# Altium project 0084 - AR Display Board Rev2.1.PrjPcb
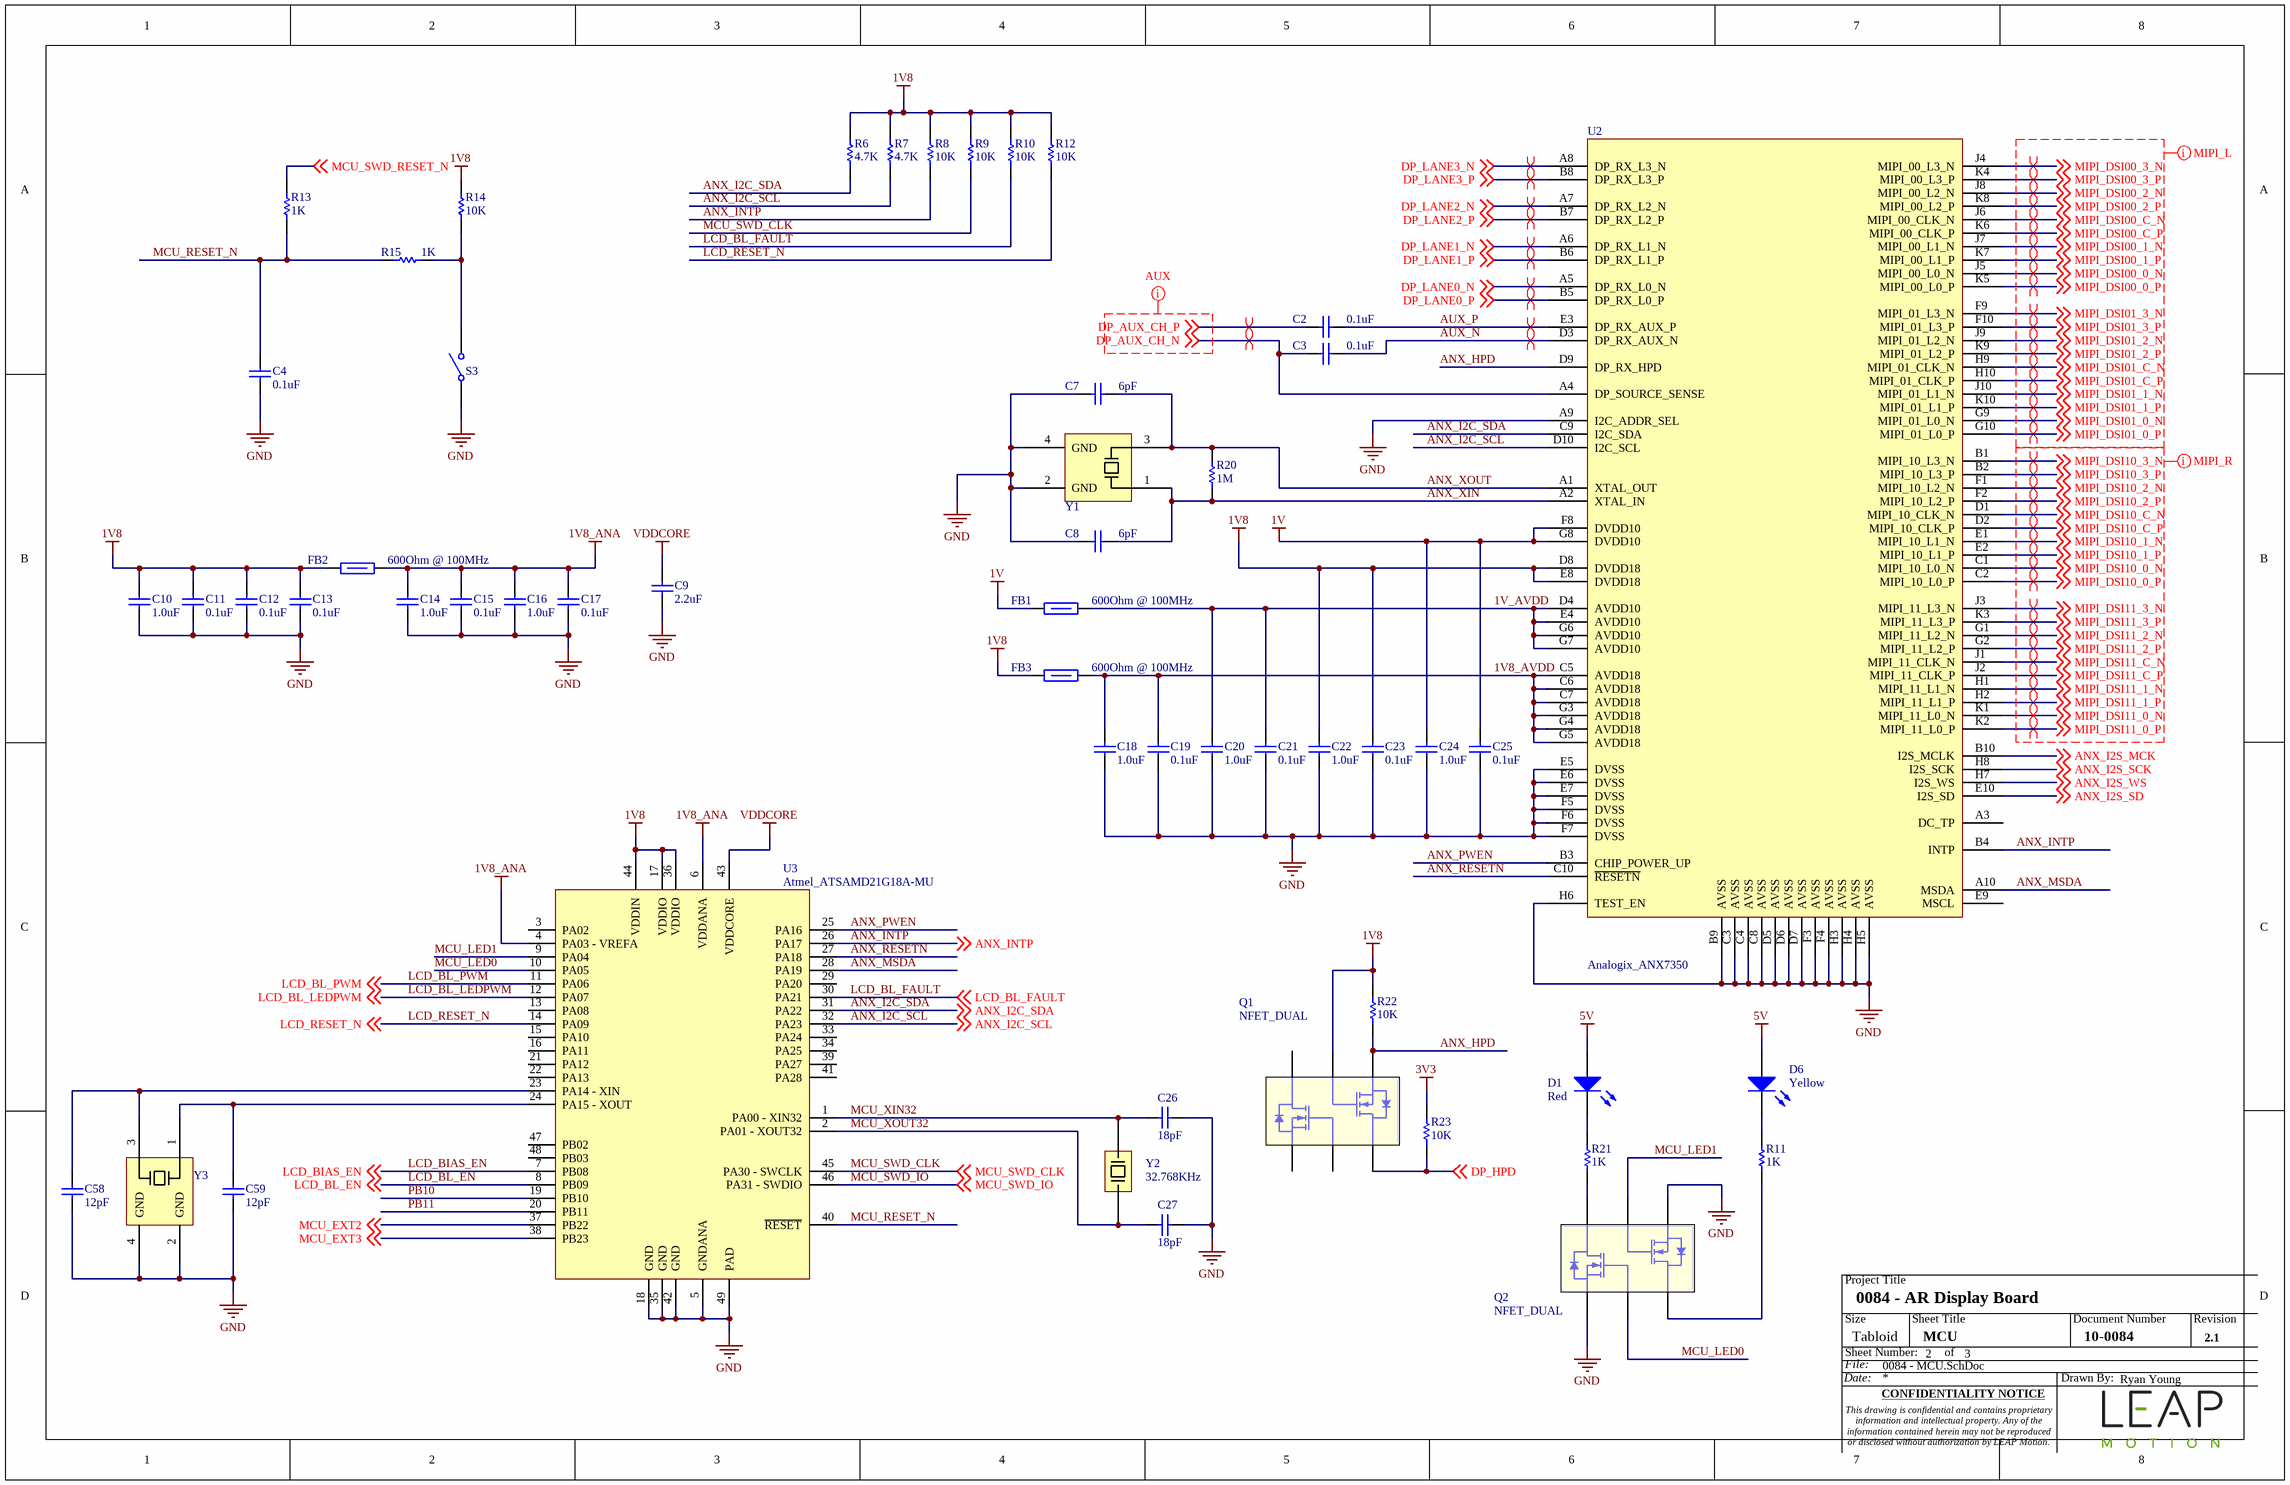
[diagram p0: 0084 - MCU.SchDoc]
BoardColor: Matte Black; BoardThickness: 1.6mm; CageCode: XXXXX; DrawnBy: Ryan Young; DrawnByDate: 3/18/2018; DwgNo: 12-0084; DwgTitle: 0084 - AR Display Board; Engineer: Ryan Young; EngineerDate: 3/18/2018; FabricatedNo: 45-0084 Rev. 002; GerberNo: 11-0084; InnerCopperWeight: 0.5 oz; IPCclass: Class 2; Issued: Ahmad Abbas; IssuedDate: 3/18/2018; OuterCopperWeight: 0.5 oz; PCBAssemblyNo: 65-0084 Rev. 002; ProjectTitle: 0084 - AR Display Board; Revision: 002; SchNo: 10-0084
3 sheets, 141 parts. Net scope: global (net labels, ports and power ports of the same name join across sheets).
Board file: 0084 - AR Display Board Rev2.1.PcbDoc
Sheets:
  0084 - MCU.SchDoc
  0084 - Power.SchDoc
  0084 - Connectors.SchDoc

## Sheet 0084 - MCU.SchDoc: 0084 - AR Display Board
size Tabloid; Date: 3/18/2018; DrawnBy: Ryan Young; DocumentNumber: 1; Revision: 2.1; SheetNumber: 2; SheetTotal: 3; SheetTitle: MCU; PageSetup: Record=PageOptions¦CenterHorizontal=True¦CenterVertical=True¦PrintScale=0.95¦XCorrection=1.00¦YCorrection=1.00¦PrintKind=0¦BorderSize=5000000¦LeftOffset=0¦BottomOffset=0¦Orientation=2¦PaperLength=1000¦PaperWidth=1000¦Scale=100¦PaperSource=15¦PrintQuality=600¦MediaType=1¦DitherType=10¦PaperKind=Letter (8.5 x 11")¦PrintScaleMode=1

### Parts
C2  0.1uF  [CAPC0201(0603)33_N]
C3  0.1uF  [CAPC0201(0603)33_N]
C4  0.1uF  [CAPC0201(0603)33_N]
C7  6pF  [CAPC0201(0603)33_N]
C8  6pF  [CAPC0201(0603)33_N]
C9  2.2uF  [CAPC0402(1005)60_N]
C10  1.0uF  [CAPC0402(1005)60_N]
C11  0.1uF  [CAPC0201(0603)33_N]
C12  0.1uF  [CAPC0201(0603)33_N]
C13  0.1uF  [CAPC0201(0603)33_N]
C14  1.0uF  [CAPC0402(1005)60_N]
C15  0.1uF  [CAPC0201(0603)33_N]
C16  1.0uF  [CAPC0402(1005)60_N]
C17  0.1uF  [CAPC0201(0603)33_N]
C18  1.0uF  [CAPC0402(1005)60_L]  (no BOM)
C19  0.1uF  [CAPC0201(0603)33_L]  (no BOM)
C20  1.0uF  [CAPC0402(1005)60_L]  (no BOM)
C21  0.1uF  [CAPC0201(0603)33_L]  (no BOM)
C22  1.0uF  [CAPC0402(1005)60_L]  (no BOM)
C23  0.1uF  [CAPC0201(0603)33_L]  (no BOM)
C24  1.0uF  [CAPC0402(1005)60_L]  (no BOM)
C25  0.1uF  [CAPC0201(0603)33_L]  (no BOM)
C26  18pF  [CAPC0201(0603)33_N]
C27  18pF  [CAPC0201(0603)33_N]
C58  12pF  [CAPC0201(0603)33_N]
C59  12pF  [CAPC0201(0603)33_N]
D1  Color: Red  [Dialight_598-8010-107F]
D6  Color: Yellow  [Dialight_598-8040-107F]
FB1  Impedance @ Freq: 600Ohm @ 100MHz  [INDC1608X09N]  (hidden comment: Ferrite Bead)
FB2  Impedance @ Freq: 600Ohm @ 100MHz  [INDC1608X09N]  (hidden comment: Ferrite Bead)
FB3  Impedance @ Freq: 600Ohm @ 100MHz  [INDC1608X09N]  (hidden comment: Ferrite Bead)
Q1  NFET_DUAL  [SOT-563]
Q2  NFET_DUAL  [SOT-563]
R6  4.7K  [RESC0201(0603)_N]
R7  4.7K  [RESC0201(0603)_N]
R8  10K  [RESC0201(0603)_N]
R9  10K  [RESC0201(0603)_N]
R10  10K  [RESC0201(0603)_N]
R11  1K  [RESC0201(0603)_N]
R12  10K  [RESC0201(0603)_N]
R13  1K  [RESC0201(0603)_N]
R14  10K  [RESC0201(0603)_N]
R15  1K  [RESC0201(0603)_N]
R20  1M  [RESC0201(0603)_N]
R21  1K  [RESC0201(0603)_N]
R22  10K  [RESC0201(0603)_N]
R23  10K  [RESC0201(0603)_N]
S3  SW-SPST  [ALPS_SKRPABE010]  (value not drawn)
U2  Analogix_ANX7350  [Analogix_ANX7350]
U3  Atmel_ATSAMD21G18A-MU  [Atmel_ATSAMD21G18A-MU]
Y1  Crystal  [Abracon_ABM11]  (value not drawn)
Y2  Frequency: 32.768KHz  [Abracon_ABS07]  (hidden comment: Crystal_2pin)
Y3  Crystal  [Abracon_ABM11]  (value not drawn)

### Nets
1V: C24.2 C25.2 FB1.1 U2.F8(DVDD10) U2.G8(DVDD10)
1V8: C10.2 C11.2 C12.2 C13.2 C22.2 C23.2 FB2.1 FB3.1 Q1.5(G2) R6.2 R7.2 R8.2 R9.2 R10.2 R12.2 R14.2 R22.2 U2.D8(DVDD18) U2.E8(DVDD18) U3.17(VDDIO) U3.36(VDDIO) U3.44(VDDIN)
1V8_ANA: C14.2 C15.2 C16.2 C17.2 FB2.2 U3.4(PA03_-_VREFA) U3.6(VDDANA)
3V3: R23.1
5V: D1.A D6.A
GND: C4.1 C7.2 C8.2 C9.2 C10.1 C11.1 C12.1 C13.1 C14.1 C15.1 C16.1 C17.1 C18.1 C19.1 C20.1 C21.1 C22.1 C23.1 C24.1 C25.1 C26.2 C27.2 C58.2 C59.2 Q2.1(S1) Q2.4(S2) S3.1(COMMON) U2.A9(I2C_ADDR_SEL) U2.B9(AVSS) U2.C3(AVSS) U2.C4(AVSS) U2.C8(AVSS) U2.D5(AVSS) U2.D6(AVSS) U2.D7(AVSS) U2.E5(DVSS) U2.E6(DVSS) U2.E7(DVSS) U2.F3(AVSS) U2.F4(AVSS) U2.F5(DVSS) U2.F6(DVSS) U2.F7(DVSS) U2.H3(AVSS) U2.H4(AVSS) U2.H5(AVSS) U2.H6(TEST_EN) U3.5(GNDANA) U3.18(GND) U3.35(GND) U3.42(GND) U3.49(PAD) Y1.2(GND) Y1.4(GND) Y3.2(GND) Y3.4(GND)
VDDCORE: C9.1 U3.43(VDDCORE)
1V8_AVDD: C18.2 C19.2 FB3.2 U2.C5(AVDD18) U2.C6(AVDD18) U2.C7(AVDD18) U2.G3(AVDD18) U2.G4(AVDD18) U2.G5(AVDD18)
1V_AVDD: C20.2 C21.2 FB1.2 U2.D4(AVDD10) U2.E4(AVDD10) U2.G6(AVDD10) U2.G7(AVDD10)
ANX_HPD: Q1.4(S2) R22.1 U2.D9(DP_RX_HPD)
ANX_I2C_SCL: R7.1 U2.D10(I2C_SCL) U3.32(PA23) ; off-sheet ANX_I2C_SCL
ANX_I2C_SDA: R6.1 U2.C9(I2C_SDA) U3.31(PA22) ; off-sheet ANX_I2C_SDA
ANX_I2S_MCK: U2.B10(I2S_MCLK) ; off-sheet ANX_I2S_MCK
ANX_I2S_SCK: U2.H8(I2S_SCK) ; off-sheet ANX_I2S_SCK
ANX_I2S_SD: U2.E10(I2S_SD) ; off-sheet ANX_I2S_SD
ANX_I2S_WS: U2.H7(I2S_WS) ; off-sheet ANX_I2S_WS
ANX_INTP: R8.1 U2.B4(INTP) U3.26(PA17) ; off-sheet ANX_INTP
ANX_MSDA: U2.A10(MSDA) U3.28(PA19)
ANX_PWEN: U2.B3(CHIP_POWER_UP) U3.25(PA16)
ANX_RESETN: U2.C10(~{RESETN}) U3.27(PA18)
ANX_XIN: C8.1 R20.1 U2.A2(XTAL_IN) Y1.1(XTAL1)
ANX_XOUT: C7.1 R20.2 U2.A1(XTAL_OUT) Y1.3(XTAL2)
AUX_N: C3.1 U2.D3(DP_RX_AUX_N)
AUX_P: C2.1 U2.E3(DP_RX_AUX_P)
DP_AUX_CH_N: C3.2 U2.A4(DP_SOURCE_SENSE) ; off-sheet DP_AUX_CH_N
DP_AUX_CH_P: C2.2 ; off-sheet DP_AUX_CH_P
DP_HPD: Q1.3(D2) R23.2 ; off-sheet DP_HPD
DP_LANE0_N: U2.A5(DP_RX_L0_N) ; off-sheet DP_LANE0_N
DP_LANE0_P: U2.B5(DP_RX_L0_P) ; off-sheet DP_LANE0_P
DP_LANE1_N: U2.A6(DP_RX_L1_N) ; off-sheet DP_LANE1_N
DP_LANE1_P: U2.B6(DP_RX_L1_P) ; off-sheet DP_LANE1_P
DP_LANE2_N: U2.A7(DP_RX_L2_N) ; off-sheet DP_LANE2_N
DP_LANE2_P: U2.B7(DP_RX_L2_P) ; off-sheet DP_LANE2_P
DP_LANE3_N: U2.A8(DP_RX_L3_N) ; off-sheet DP_LANE3_N
DP_LANE3_P: U2.B8(DP_RX_L3_P) ; off-sheet DP_LANE3_P
LCD_BIAS_EN: U3.7(PB08) ; off-sheet LCD_BIAS_EN
LCD_BL_EN: U3.8(PB09) ; off-sheet LCD_BL_EN
LCD_BL_FAULT: R10.1 U3.30(PA21) ; off-sheet LCD_BL_FAULT
LCD_BL_LEDPWM: U3.12(PA07) ; off-sheet LCD_BL_LEDPWM
LCD_BL_PWM: U3.11(PA06) ; off-sheet LCD_BL_PWM
LCD_RESET_N: R12.1 U3.14(PA09) ; off-sheet LCD_RESET_N
MCU_EXT2: U3.37(PB22) ; off-sheet MCU_EXT2
MCU_EXT3: U3.38(PB23) ; off-sheet MCU_EXT3
MCU_LED0: Q2.2(G1) U3.10(PA05)
MCU_LED1: Q2.5(G2) U3.9(PA04)
MCU_RESET_N: C4.2 R13.2 R15.2 U3.40(~{RESET})
MCU_SWD_CLK: R9.1 U3.45(PA30_-_SWCLK) ; off-sheet MCU_SWD_CLK
MCU_SWD_IO: U3.46(PA31_-_SWDIO) ; off-sheet MCU_SWD_IO
MCU_SWD_RESET_N: R13.1 ; off-sheet MCU_SWD_RESET_N
MCU_XIN32: C26.1 U3.1(PA00_-_XIN32) Y2.1(XTAL2)
MCU_XOUT32: C27.1 U3.2(PA01_-_XOUT32) Y2.0(XTAL1)
MIPI_DSI00_0_N: U2.J5(MIPI_00_L0_N) ; off-sheet MIPI_DSI00_0_N
MIPI_DSI00_0_P: U2.K5(MIPI_00_L0_P) ; off-sheet MIPI_DSI00_0_P
MIPI_DSI00_1_N: U2.J7(MIPI_00_L1_N) ; off-sheet MIPI_DSI00_1_N
MIPI_DSI00_1_P: U2.K7(MIPI_00_L1_P) ; off-sheet MIPI_DSI00_1_P
MIPI_DSI00_2_N: U2.J8(MIPI_00_L2_N) ; off-sheet MIPI_DSI00_2_N
MIPI_DSI00_2_P: U2.K8(MIPI_00_L2_P) ; off-sheet MIPI_DSI00_2_P
MIPI_DSI00_3_N: U2.J4(MIPI_00_L3_N) ; off-sheet MIPI_DSI00_3_N
MIPI_DSI00_3_P: U2.K4(MIPI_00_L3_P) ; off-sheet MIPI_DSI00_3_P
MIPI_DSI00_C_N: U2.J6(MIPI_00_CLK_N) ; off-sheet MIPI_DSI00_C_N
MIPI_DSI00_C_P: U2.K6(MIPI_00_CLK_P) ; off-sheet MIPI_DSI00_C_P
MIPI_DSI01_0_N: U2.G9(MIPI_01_L0_N) ; off-sheet MIPI_DSI01_0_N
MIPI_DSI01_0_P: U2.G10(MIPI_01_L0_P) ; off-sheet MIPI_DSI01_0_P
MIPI_DSI01_1_N: U2.J10(MIPI_01_L1_N) ; off-sheet MIPI_DSI01_1_N
MIPI_DSI01_1_P: U2.K10(MIPI_01_L1_P) ; off-sheet MIPI_DSI01_1_P
MIPI_DSI01_2_N: U2.J9(MIPI_01_L2_N) ; off-sheet MIPI_DSI01_2_N
MIPI_DSI01_2_P: U2.K9(MIPI_01_L2_P) ; off-sheet MIPI_DSI01_2_P
MIPI_DSI01_3_N: U2.F9(MIPI_01_L3_N) ; off-sheet MIPI_DSI01_3_N
MIPI_DSI01_3_P: U2.F10(MIPI_01_L3_P) ; off-sheet MIPI_DSI01_3_P
MIPI_DSI01_C_N: U2.H9(MIPI_01_CLK_N) ; off-sheet MIPI_DSI01_C_N
MIPI_DSI01_C_P: U2.H10(MIPI_01_CLK_P) ; off-sheet MIPI_DSI01_C_P
MIPI_DSI10_0_N: U2.C1(MIPI_10_L0_N) ; off-sheet MIPI_DSI10_0_N
MIPI_DSI10_0_P: U2.C2(MIPI_10_L0_P) ; off-sheet MIPI_DSI10_0_P
MIPI_DSI10_1_N: U2.E1(MIPI_10_L1_N) ; off-sheet MIPI_DSI10_1_N
MIPI_DSI10_1_P: U2.E2(MIPI_10_L1_P) ; off-sheet MIPI_DSI10_1_P
MIPI_DSI10_2_N: U2.F1(MIPI_10_L2_N) ; off-sheet MIPI_DSI10_2_N
MIPI_DSI10_2_P: U2.F2(MIPI_10_L2_P) ; off-sheet MIPI_DSI10_2_P
MIPI_DSI10_3_N: U2.B1(MIPI_10_L3_N) ; off-sheet MIPI_DSI10_3_N
MIPI_DSI10_3_P: U2.B2(MIPI_10_L3_P) ; off-sheet MIPI_DSI10_3_P
MIPI_DSI10_C_N: U2.D1(MIPI_10_CLK_N) ; off-sheet MIPI_DSI10_C_N
MIPI_DSI10_C_P: U2.D2(MIPI_10_CLK_P) ; off-sheet MIPI_DSI10_C_P
MIPI_DSI11_0_N: U2.K1(MIPI_11_L0_N) ; off-sheet MIPI_DSI11_0_N
MIPI_DSI11_0_P: U2.K2(MIPI_11_L0_P) ; off-sheet MIPI_DSI11_0_P
MIPI_DSI11_1_N: U2.H1(MIPI_11_L1_N) ; off-sheet MIPI_DSI11_1_N
MIPI_DSI11_1_P: U2.H2(MIPI_11_L1_P) ; off-sheet MIPI_DSI11_1_P
MIPI_DSI11_2_N: U2.G1(MIPI_11_L2_N) ; off-sheet MIPI_DSI11_2_N
MIPI_DSI11_2_P: U2.G2(MIPI_11_L2_P) ; off-sheet MIPI_DSI11_2_P
MIPI_DSI11_3_N: U2.J3(MIPI_11_L3_N) ; off-sheet MIPI_DSI11_3_N
MIPI_DSI11_3_P: U2.K3(MIPI_11_L3_P) ; off-sheet MIPI_DSI11_3_P
MIPI_DSI11_C_N: U2.J1(MIPI_11_CLK_N) ; off-sheet MIPI_DSI11_C_N
MIPI_DSI11_C_P: U2.J2(MIPI_11_CLK_P) ; off-sheet MIPI_DSI11_C_P
PB10: U3.19(PB10)
PB11: U3.20(PB11)
NetC58_1: C58.1 U3.23(PA14_-_XIN) Y3.3(XTAL2)
NetC59_1: C59.1 U3.24(PA15_-_XOUT) Y3.1(XTAL1)
NetD1_K: D1.K R21.1
NetD6_K: D6.K R11.1
NetQ2_3: Q2.3(D2) R11.2
NetQ2_6: Q2.6(D1) R21.2
NetR14_1: R14.1 R15.1 S3.2(NO)

Not connected (* = marked no-connect by the designer): Q1 1(S1) 2(G1) 6(D1); U2 A3(DC_TP) E9(MSCL); U3 3(PA02) 13(PA08) 15(PA10) 16(PA11) 21(PA12) 22(PA13) 29(PA20) 33(PA24) 34(PA25) 39(PA27) 41(PA28) 47(PB02) 48(PB03)

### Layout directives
differential pair: AUX_N, AUX_P, DP_AUX_CH_N, DP_AUX_CH_P, DP_LANE0_N, DP_LANE0_P, DP_LANE1_N, DP_LANE1_P, DP_LANE2_N, DP_LANE2_P, DP_LANE3_N, DP_LANE3_P, MIPI_DSI00_0_N, MIPI_DSI00_0_P, MIPI_DSI00_1_N, MIPI_DSI00_1_P, MIPI_DSI00_2_N, MIPI_DSI00_2_P, MIPI_DSI00_3_N, MIPI_DSI00_3_P, MIPI_DSI00_C_N, MIPI_DSI00_C_P, MIPI_DSI01_0_N, MIPI_DSI01_0_P, MIPI_DSI01_1_N, MIPI_DSI01_1_P, MIPI_DSI01_2_N, MIPI_DSI01_2_P, MIPI_DSI01_3_N, MIPI_DSI01_3_P, MIPI_DSI01_C_N, MIPI_DSI01_C_P, MIPI_DSI10_0_N, MIPI_DSI10_0_P, MIPI_DSI10_1_N, MIPI_DSI10_1_P, MIPI_DSI10_2_N, MIPI_DSI10_2_P, MIPI_DSI10_3_N, MIPI_DSI10_3_P, MIPI_DSI10_C_N, MIPI_DSI10_C_P, MIPI_DSI11_0_N, MIPI_DSI11_0_P, MIPI_DSI11_1_N, MIPI_DSI11_1_P, MIPI_DSI11_2_N, MIPI_DSI11_2_P, MIPI_DSI11_3_N, MIPI_DSI11_3_P, MIPI_DSI11_C_N, MIPI_DSI11_C_P
net class MIPI_L: MIPI_DSI00_0_N, MIPI_DSI00_0_P, MIPI_DSI00_1_N, MIPI_DSI00_1_P, MIPI_DSI00_2_N, MIPI_DSI00_2_P, MIPI_DSI00_3_N, MIPI_DSI00_3_P, MIPI_DSI00_C_N, MIPI_DSI00_C_P, MIPI_DSI01_0_N, MIPI_DSI01_0_P, MIPI_DSI01_1_N, MIPI_DSI01_1_P, MIPI_DSI01_2_N, MIPI_DSI01_2_P, MIPI_DSI01_3_N, MIPI_DSI01_3_P, MIPI_DSI01_C_N, MIPI_DSI01_C_P
net class MIPI_R: MIPI_DSI10_0_N, MIPI_DSI10_0_P, MIPI_DSI10_1_N, MIPI_DSI10_1_P, MIPI_DSI10_2_N, MIPI_DSI10_2_P, MIPI_DSI10_3_N, MIPI_DSI10_3_P, MIPI_DSI10_C_N, MIPI_DSI10_C_P, MIPI_DSI11_0_N, MIPI_DSI11_0_P, MIPI_DSI11_1_N, MIPI_DSI11_1_P, MIPI_DSI11_2_N, MIPI_DSI11_2_P, MIPI_DSI11_3_N, MIPI_DSI11_3_P, MIPI_DSI11_C_N, MIPI_DSI11_C_P
net class AUX: DP_AUX_CH_N, DP_AUX_CH_P

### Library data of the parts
C2-C4 C11-C13 C15 C17 C19 C21 C23 C25 = CAP_0060: Capacitor, 0.1uF, 10V, 10%, 0201, Ceramic, X5R; Manufacturer: Murata; Manufacturer P/N: GRM033R61A104KE15D; Polarity: No; Temp Range: -55C - 85C
C7 C8 = CAP_0064: Capacitor, 6pF, 50V, 0.1pF, 0201, Ceramic, C0G(NP0); Manufacturer: Murata; Manufacturer P/N: GRM0335C1H6R0BA01D; Polarity: No; Temp Range: -55C - 125C
C9 = CAP_0016: Capacitor, 2.2uF, 6.3V, 20%, 0402, Ceramic, X5R; Manufacturer: TDK; Manufacturer P/N: C1005X5R0J225M050BC; Polarity: No; Temp Range: -55C - 85C
C10 C14 C16 C18 C20 C22 C24 = CAP_0023: Capacitor, 1.0uF, 10V, 10%, 0402, Ceramic, X5R; Manufacturer: TDK; Manufacturer P/N: C1005X5R1A105K050BB; Polarity: No; Temp Range: -55C - 85C
C26 C27 = CAP_0066: Capacitor, 18pF, 50V, 2%, 0201, Ceramic, C0G(NP0); Manufacturer: Murata; Manufacturer P/N: GRM0335C1H180GA01D; Polarity: No; Temp Range: -55C - 125C
C58 C59 = CAP_0065: Capacitor, 12pF, 50V, 2%, 0201, Ceramic, C0G(NP0); Manufacturer: Murata; Manufacturer P/N: GRM0335C1H120GA01D; Polarity: No; Temp Range: -55C - 125C
D1 = LED_0017: LED, 635nm, 140deg, , 20mA, , 1.6mm x 0.8mm, -30C - 85C; Manufacturer: Dialight; Manufacturer P/N: 598-8010-107F; Vf: 1.7V; Radiant Intensity (mW/sr): 40mcd
D6 = LED_0034: LED, 593nm, 140deg, , 20mA, , 1.6mm x 0.8mm, -30C - 85C; Manufacturer: Dialight; Manufacturer P/N: 598-8040-107F; Vf: 2V; Radiant Intensity (mW/sr): 130mcd
FB1-FB3 = FB_0001: FERRITE CHIP BEAD 600 OHM SMD; Manufacturer: TDK; Manufacturer P/N: MPZ1608S601A; Current Rating: 1A; DCR: 150mOhm
Q1 Q2 = NFET_0009: Transistor, NFET_DUAL, 2.2Ohm, 200mA, 120mW, 	SOT-563, -55C - 150C; Manufacturer: Rohm Semiconductor; Manufacturer P/N: EM6K34T2CR; Display: NFET_DUAL, 	SOT-563
R6 R7 = RES_0040: Resistor, 4.7K, 1/20W, 1%, 0201; Manufacturer: Panasonic Electronic Components; Manufacturer P/N: ERJ-1GEF4701C; Display Value: 4.7K, 0201; Temp Range: -55C - 125C
R8-R10 R12 R14 R22 R23 = RES_0014: Resistor, 10K, 1/20W, 5%, 0201; Manufacturer: Panasonic Electronic Components; Manufacturer P/N: ERJ-1GEJ103C; Display Value: 10K, 0201; Temp Range: -55C - 155C
R11 R13 R15 R21 = RES_0036: Resistor, 1K, 1/20W, 5%, 0201; Manufacturer: Panasonic Electronic Components; Manufacturer P/N: ERJ-1GEJ102C; Display Value: 1K, 0201; Temp Range: -55C - 125C
R20 = RES_0178: Resistor, 1M, 1/20W, 1%, 0201; Manufacturer: Panasonic Electronic Components; Manufacturer P/N: ERJ-1GEF1004C; Display Value: 1M, 0201; Temp Range: -55C - 125C
S3 = SWT_0006: Switch, SPST-NO, Button, 4.6mm x 3.2mm; Manufacturer: ALPS; Manufacturer P/N: SKRPABE010; Display: Switch, SW-SPST
U2 = IC_0196: DisplayPort 1.4-to-Dual MIPI Output Converter
U3 = IC_0197: IC MCU 32BIT 256KB FLASH 48QFN; Manufacturer: Atmel
Y1 = XTAL_0025: Crystal, 24MHz, 6pF, 4-SMD (2x1.6); Manufacturer: Abracon; Manufacturer P/N: XRCGB24M000F2P0R0; Tolerance: 20ppm
Y2 = XTAL_0023: Crystal, 32.768KHz, 12.5pF, 2-SMD(3.2x1.5); Manufacturer: Abracon; Manufacturer P/N: ABS07-32.768KHZ-T; Tolerance: 20 ppm
Y3 = XTAL_0024: Crystal, 16MHz, 10pF, 4-SMD (2x1.6); Manufacturer: Abracon; Manufacturer P/N: ABM11-16.000MHZ-D2X-T3; Tolerance: 20ppm

## Sheet 0084 - Power.SchDoc: 0084 - AR Display
size Tabloid; Date: 3/18/2018; DrawnBy: Ryan Young; DocumentNumber: 1; Revision: 2.1; SheetNumber: 1; SheetTotal: 3; SheetTitle: Power; PageSetup: Record=PageOptions¦CenterHorizontal=True¦CenterVertical=True¦PrintScale=0.95¦XCorrection=1.00¦YCorrection=1.00¦PrintKind=0¦BorderSize=5000000¦LeftOffset=0¦BottomOffset=0¦Orientation=2¦PaperLength=1000¦PaperWidth=1000¦Scale=100¦PaperSource=15¦PrintQuality=600¦MediaType=1¦DitherType=10¦PaperKind=Letter (8.5 x 11")¦PrintScaleMode=1
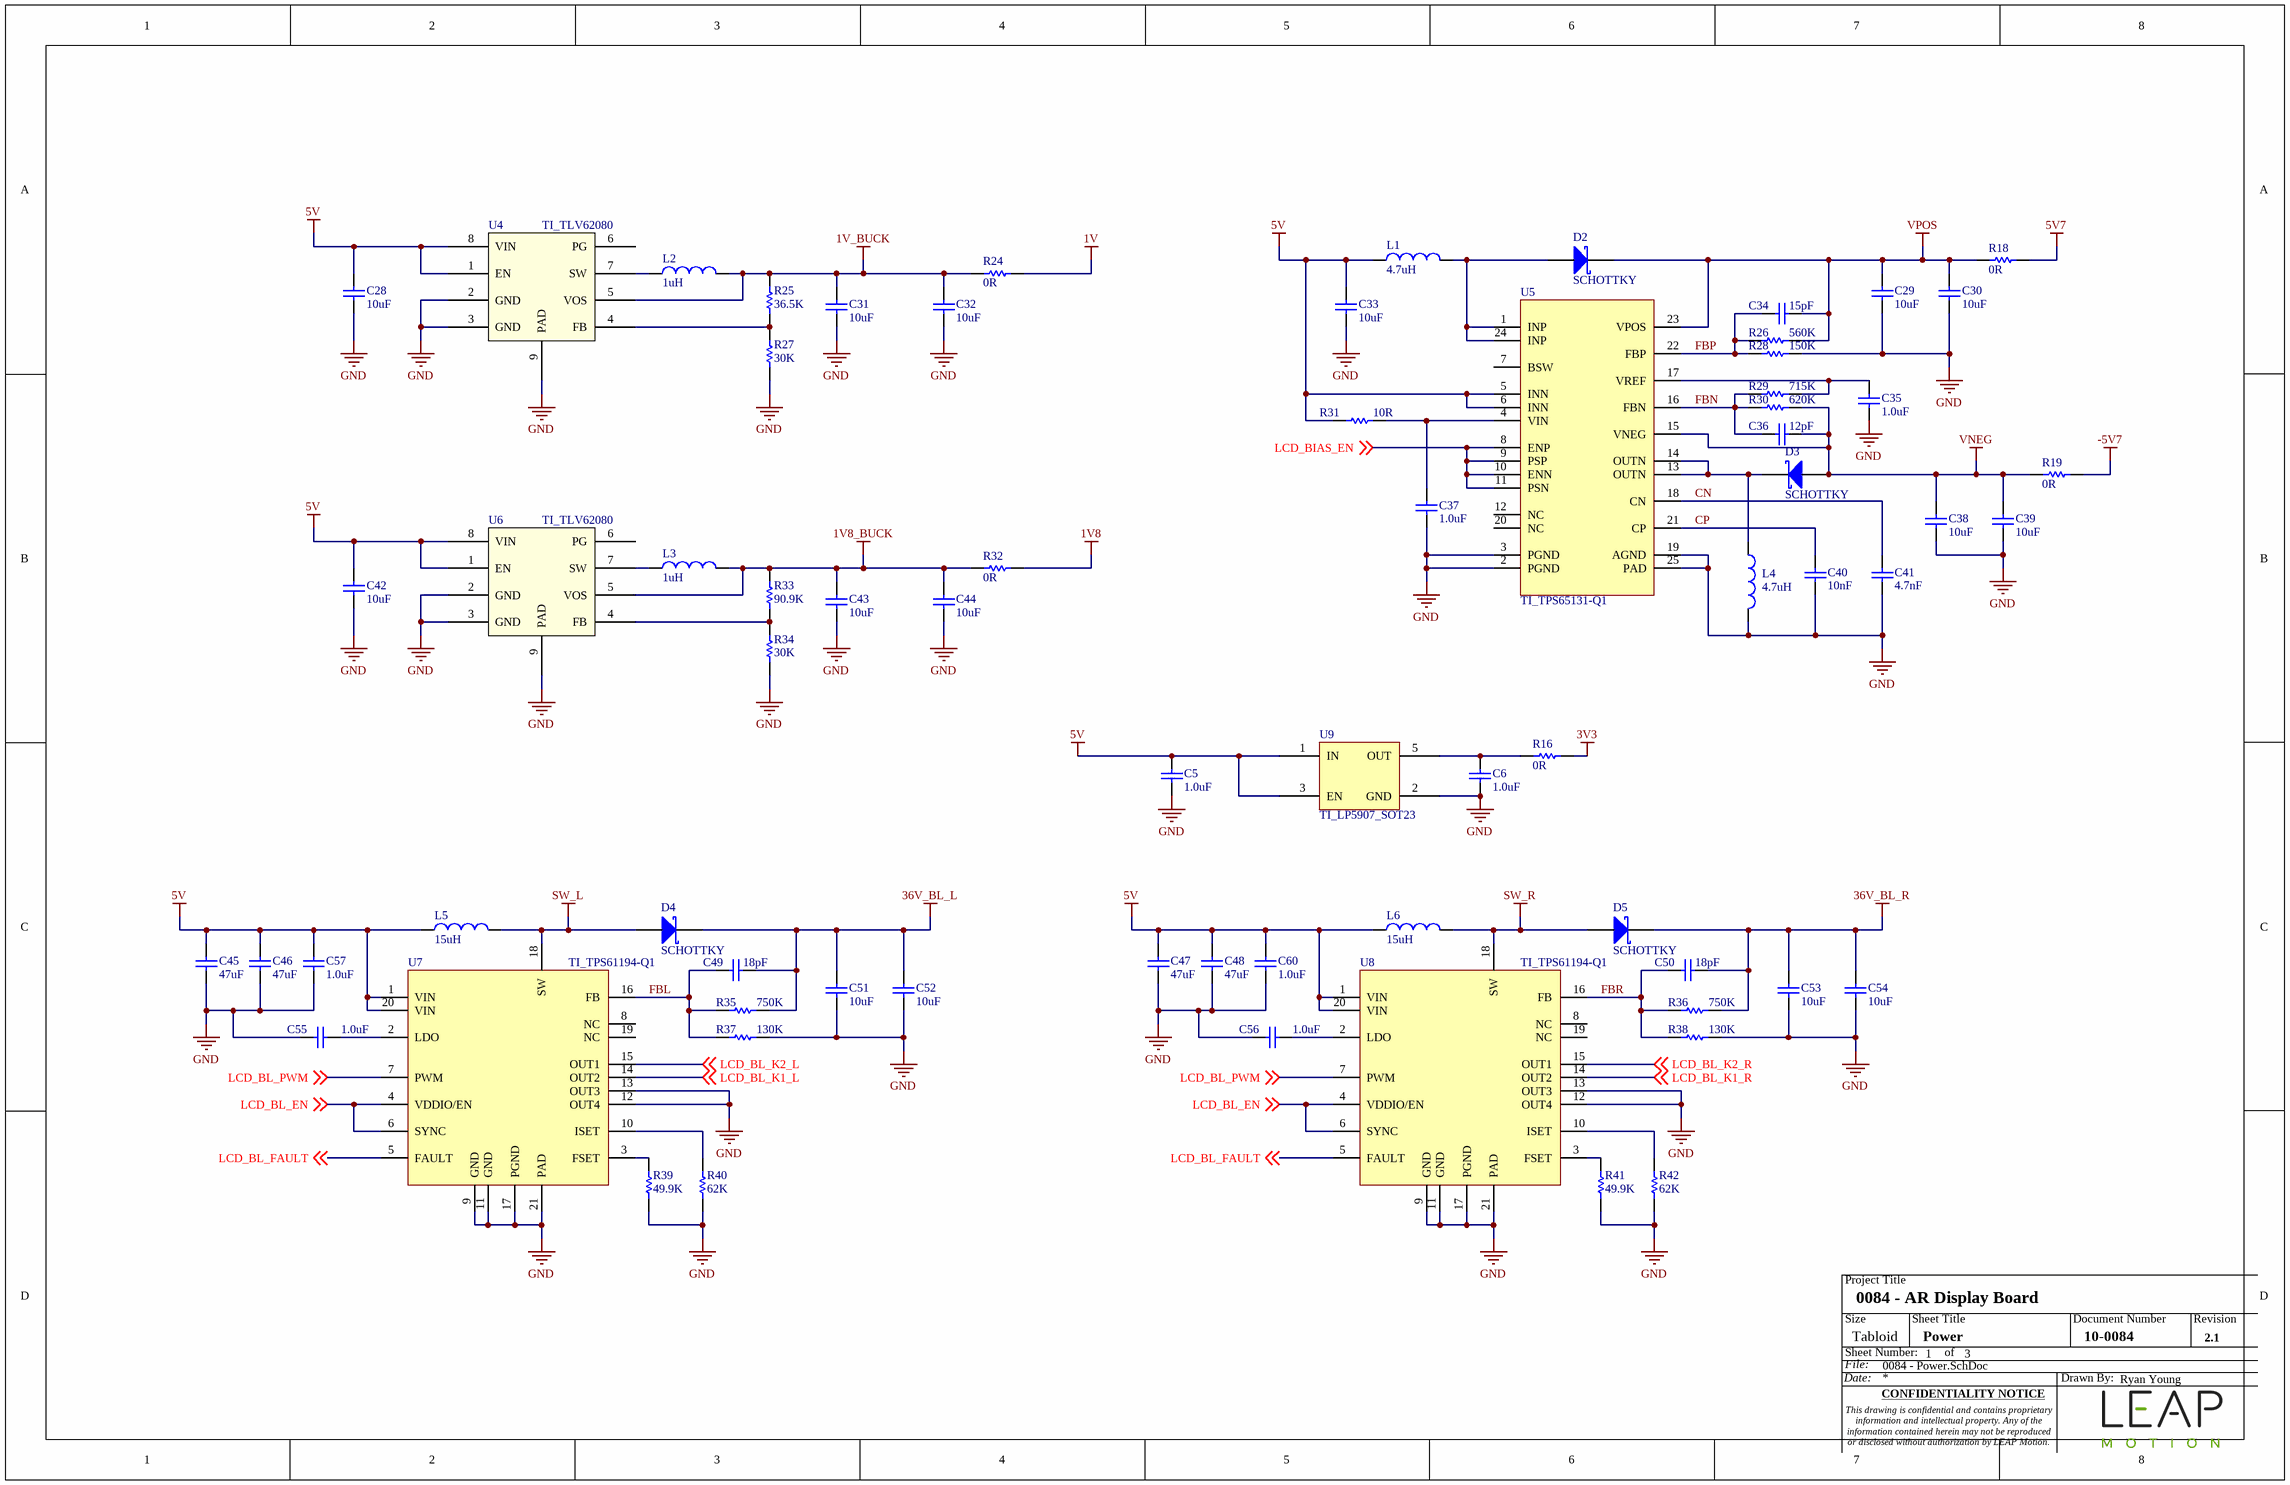
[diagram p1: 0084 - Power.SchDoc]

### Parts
C5  1.0uF  [CAPC0402(1005)60_N]
C6  1.0uF  [CAPC0402(1005)60_N]
C28  10uF  [CAPC0603(1608)100_N]
C29  10uF  [CAPC0603(1608)100_N]
C30  10uF  [CAPC0603(1608)100_N]
C31  10uF  [CAPC0603(1608)100_N]
C32  10uF  [CAPC0603(1608)100_N]
C33  10uF  [CAPC0603(1608)100_N]
C34  15pF  [CAPC0201(0603)33_N]
C35  1.0uF  [CAPC0402(1005)60_N]
C36  12pF  [CAPC0201(0603)33_N]
C37  1.0uF  [CAPC0402(1005)60_N]
C38  10uF  [CAPC0603(1608)100_N]
C39  10uF  [CAPC0603(1608)100_N]
C40  10nF  [CAPC0402(1005)60_N]
C41  4.7nF  [CAPC0402(1005)60_N]
C42  10uF  [CAPC0603(1608)100_N]
C43  10uF  [CAPC0603(1608)100_N]
C44  10uF  [CAPC0603(1608)100_N]
C45  47uF  [CAPC0805(2012)100_N]
C46  47uF  [CAPC0805(2012)100_N]
C47  47uF  [CAPC0805(2012)100_N]
C48  47uF  [CAPC0805(2012)100_N]
C49  18pF  [CAPC0201(0603)33_N]
C50  18pF  [CAPC0201(0603)33_N]
C51  10uF  [CAPC1206(3216)170_N]
C52  10uF  [CAPC1206(3216)170_N]
C53  10uF  [CAPC1206(3216)170_N]
C54  10uF  [CAPC1206(3216)170_N]
C55  1.0uF  [CAPC0402(1005)60_N]
C56  1.0uF  [CAPC0402(1005)60_N]
C57  1.0uF  [CAPC0402(1005)60_N]
C60  1.0uF  [CAPC0402(1005)60_N]
D2  SCHOTTKY  [Toshiba_CUS10S40,H3F]
D3  SCHOTTKY  [Toshiba_CUS10S40,H3F]
D4  SCHOTTKY  [Toshiba_CUS10S40,H3F]
D5  SCHOTTKY  [Toshiba_CUS10S40,H3F]
L1  4.7uH  [INDC2520X10N]
L2  1uH  [INDC2520X10N]
L3  1uH  [INDC2520X10N]
L4  4.7uH  [INDC2520X10N]
L5  15uH  [Coilcraft_XAL4040-153MEB]
L6  15uH  [Coilcraft_XAL4040-153MEB]
R16  0R  [RESC0402(1005)_N]
R18  0R  [RESC0402(1005)_N]
R19  0R  [RESC0402(1005)_N]
R24  0R  [RESC0402(1005)_N]
R25  36.5K  [RESC0201(0603)_N]
R26  560K  [RESC0201(0603)_N]
R27  30K  [RESC0201(0603)_N]
R28  150K  [RESC0201(0603)_N]
R29  715K  [RESC0201(0603)_N]
R30  620K  [RESC0201(0603)_N]
R31  10R  [RESC0402(1005)_N]
R32  0R  [RESC0402(1005)_N]
R33  90.9K  [RESC0201(0603)_N]
R34  30K  [RESC0201(0603)_N]
R35  750K  [RESC0201(0603)_N]
R36  750K  [RESC0201(0603)_N]
R37  130K  [RESC0201(0603)_N]
R38  130K  [RESC0201(0603)_N]
R39  49.9K  [RESC0201(0603)_N]
R40  62K  [RESC0201(0603)_N]
R41  49.9K  [RESC0201(0603)_N]
R42  62K  [RESC0201(0603)_N]
U4  TI_TLV62080  [TI_TLV62080]
U5  TI_TPS65131-Q1  [TI_TPS65131-Q1]
U6  TI_TLV62080  [TI_TLV62080]
U7  TI_TPS61194-Q1  [TI_TPS61194-Q1]
U8  TI_TPS61194-Q1  [TI_TPS61194-Q1]
U9  TI_LP5907_SOT23  [TI_LP5907_SOT23]

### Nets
1V: R24.2
1V8: R32.2
1V8_BUCK: C43.2 C44.2 L3.2 R32.1 R33.2 U6.5(VOS)
1V_BUCK: C31.2 C32.2 L2.2 R24.1 R25.2 U4.5(VOS)
3V3: R16.2
5V: C5.1 C28.2 C33.2 C42.2 C45.2 C46.2 C47.2 C48.2 C57.2 C60.2 L1.1 L5.1 L6.1 R31.1 U4.1(EN) U4.8(VIN) U5.5(INN) U5.6(INN) U6.1(EN) U6.8(VIN) U7.1(VIN) U7.20(VIN) U8.1(VIN) U8.20(VIN) U9.1(IN) U9.3(EN)
5V7: R18.2
36V_BL_L: C49.1 C51.2 C52.2 D4.K R35.1
36V_BL_R: C50.1 C53.2 C54.2 D5.K R36.1
-5V7: R19.2
GND: C5.2 C6.2 C28.1 C29.1 C30.1 C31.1 C32.1 C33.1 C35.2 C37.1 C38.1 C39.1 C40.2 C41.2 C42.1 C43.1 C44.1 C45.1 C46.1 C47.1 C48.1 C51.1 C52.1 C53.1 C54.1 C55.2 C56.2 C57.1 C60.1 L4.2 R27.1 R28.1 R34.1 R37.1 R38.1 R39.1 R40.1 R41.1 R42.1 U4.2(GND) U4.3(GND) U4.9(PAD) U5.2(PGND) U5.3(PGND) U5.19(AGND) U5.25(PAD) U6.2(GND) U6.3(GND) U6.9(PAD) U7.9(GND) U7.11(GND) U7.12(OUT4) U7.13(OUT3) U7.17(PGND) U7.21(PAD) U8.9(GND) U8.11(GND) U8.12(OUT4) U8.13(OUT3) U8.17(PGND) U8.21(PAD) U9.2(GND)
SW_L: D4.A L5.2 U7.18(SW)
SW_R: D5.A L6.2 U8.18(SW)
VNEG: C36.1 C38.2 C39.2 D3.A R19.1 R30.1 U5.15(VNEG)
VPOS: C29.2 C30.2 C34.1 D2.K R18.1 R26.1 U5.23(VPOS)
CN: C41.1 U5.18(CN)
CP: C40.1 U5.21(CP)
FBL: C49.2 R35.2 R37.2 U7.16(FB)
FBN: C36.2 R29.2 R30.2 U5.16(FBN)
FBP: C34.2 R26.2 R28.2 U5.22(FBP)
FBR: C50.2 R36.2 R38.2 U8.16(FB)
LCD_BIAS_EN: U5.8(ENP) U5.9(PSP) U5.10(ENN) U5.11(PSN) ; off-sheet LCD_BIAS_EN
LCD_BL_EN: U7.4(VDDIO/EN) U7.6(SYNC) U8.4(VDDIO/EN) U8.6(SYNC) ; off-sheet LCD_BL_EN
LCD_BL_FAULT: U7.5(FAULT) U8.5(FAULT) ; off-sheet LCD_BL_FAULT
LCD_BL_K1_L: U7.14(OUT2) ; off-sheet LCD_BL_K1_L
LCD_BL_K1_R: U8.14(OUT2) ; off-sheet LCD_BL_K1_R
LCD_BL_K2_L: U7.15(OUT1) ; off-sheet LCD_BL_K2_L
LCD_BL_K2_R: U8.15(OUT1) ; off-sheet LCD_BL_K2_R
LCD_BL_PWM: U7.7(PWM) U8.7(PWM) ; off-sheet LCD_BL_PWM
NetC6_1: C6.1 R16.1 U9.5(OUT)
NetC35_1: C35.1 R29.1 U5.17(VREF)
NetC37_2: C37.2 R31.2 U5.4(VIN)
NetC55_1: C55.1 U7.2(LDO)
NetC56_1: C56.1 U8.2(LDO)
NetD2_A: D2.A L1.2 U5.1(INP) U5.24(INP)
NetD3_K: D3.K L4.1 U5.13(OUTN) U5.14(OUTN)
NetL2_1: L2.1 U4.7(SW)
NetL3_1: L3.1 U6.7(SW)
NetR25_1: R25.1 R27.2 U4.4(FB)
NetR33_1: R33.1 R34.2 U6.4(FB)
NetR39_2: R39.2 U7.3(FSET)
NetR40_2: R40.2 U7.10(ISET)
NetR41_2: R41.2 U8.3(FSET)
NetR42_2: R42.2 U8.10(ISET)

Not connected (* = marked no-connect by the designer): U4 6(PG); U5 7(BSW) 12(NC) 20(NC); U6 6(PG); U7 8(NC) 19(NC); U8 8(NC) 19(NC); U9 4(NC)

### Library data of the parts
C5 C6 C35 C37 C40 C41 C55-C57 C60 = CAP_0023: as C10 on sheet 0084 - MCU
C28-C33 C38 C39 C42-C44 = CAP_0069: Capacitor, 10uF, 10V, 10%, 0603, Ceramic, X5R; Manufacturer: Murata; Manufacturer P/N: GRM188R61A106KE69D; Polarity: No; Temp Range: -55C - 85C
C34 = CAP_0067: Capacitor, 15pF, 50V, 2%, 0201, Ceramic, C0G(NP0); Manufacturer: Murata; Manufacturer P/N: GRM0335C1H150GA01D; Polarity: No; Temp Range: -55C - 125C
C36 = CAP_0065: as C58 on sheet 0084 - MCU
C45-C48 = CAP_0050: Capacitor, 47uF, 10V, 20%, 0805, Ceramic, X5R; Manufacturer: Murata; Manufacturer P/N: GRM21BR61A476ME15L; Polarity: No; Temp Range: -55C-125C
C49 C50 = CAP_0066: as C26 on sheet 0084 - MCU
C51-C54 = CAP_0068: Capacitor, 10uF, 50V, 10%, 1206, Ceramic, X7R; Manufacturer: Samsung; Manufacturer P/N: CL31B106KBHNNNE; Polarity: No; Temp Range: -55C - 125C
D2-D5 = DIODE_0020: Diode, -40C - 150C, SOD-323; Manufacturer: Toshiba; Manufacturer P/N: CUS10S40,H3F
L1 L4 = IND_0023: FIXED IND 4.7UH 1.4A 216 MOHM; Manufacturer: Murata; Manufacturer P/N: DFE252012R-H-4R7M=P2; Tolerance: 20%; Shielding: Shielded
L2 L3 = IND_0001: INDUCTOR 1.0UH 20% 1600MA 1008; Manufacturer: Murata; Manufacturer P/N: LQM2HPN1R0MG0L; Current Rating: 1.6A; Shielding: Shielded; DCR: 68.75mOhm
L5 L6 = IND_0026: Fixed Inductors XAL4040 AEC-Q200 15 uH 20 % 2.8 A; Manufacturer: Coilcraft; Manufacturer P/N: XAL4040-153MEB; Current Rating: 2.8A; Tolerance: 20%; Shielding: Shielded; DCR: 120mOhm
R16 R18 R19 R24 R32 = RES_0006: Resistor, 0R, 1/10W, Jumper, 0402; Manufacturer: Panasonic Electronic Components; Manufacturer P/N: ERJ-2GE0R00X; Display Value: 0R, 0402; Temp Range: -55C - 155C
R25 = RES_0176: Resistor, 36.5K, 1/20W, 1%, 0201; Manufacturer: Panasonic Electronic Components; Manufacturer P/N: ERJ-1GEF3652C; Display Value: 36.5K, 0201; Temp Range: -55C - 125C
R26 = RES_0194: Resistor, 560K, 1/20W, 1%, 0201; Manufacturer: Yageo; Manufacturer P/N: RC0201FR-07560KL; Display Value: 560K, 0201; Temp Range: -55C - 125C
R27 R34 = RES_0175: Resistor, 30K, 1/20W, 1%, 0201; Manufacturer: Panasonic Electronic Components; Manufacturer P/N: ERJ-1GEF3002C; Display Value: 30K, 0201; Temp Range: -55C - 125C
R28 = RES_0173: Resistor, 150K, 1/20W, 1%, 0201; Manufacturer: Panasonic Electronic Components; Manufacturer P/N: ERJ-1GEF1503C; Display Value: 150K, 0201; Temp Range: -55C - 125C
R29 = RES_0195: Resistor, 715K, 1/20W, 1%, 0201; Manufacturer: Yageo; Manufacturer P/N: RC0201FR-07715KL; Display Value: 715K, 0201; Temp Range: -55C - 125C
R30 = RES_0174: Resistor, 620K, 1/20W, 1%, 0201; Manufacturer: Panasonic Electronic Components; Manufacturer P/N: ERJ-1GEF6203C; Display Value: 620K, 0201; Temp Range: -55C - 125C
R31 = RES_0094: Resistor, 10R, 1/10W, 1%, 0402; Manufacturer: Panasonic; Manufacturer P/N: ERJ-2RKF10R0X; Display Value: 10R, 0402; Temp Range: -55C - 155C
R33 = RES_0177: Resistor, 90.9K, 1/20W, 1%, 0201; Manufacturer: Panasonic Electronic Components; Manufacturer P/N: ERJ-1GEF9092C; Display Value: 90.9K, 0201; Temp Range: -55C - 125C
R35 R36 = RES_0169: Resistor, 750K, 1/20W, 1%, 0201; Manufacturer: Panasonic Electronic Components; Manufacturer P/N: ERJ-1GEF7503C; Display Value: 750K, 0201; Temp Range: -55C - 125C
R37 R38 = RES_0170: Resistor, 130K, 1/20W, 1%, 0201; Manufacturer: Panasonic Electronic Components; Manufacturer P/N: ERJ-1GEF1303C; Display Value: 130K, 0201; Temp Range: -55C - 125C
R39 R41 = RES_0067: Resistor, 49.9K, 1/20W, 1%, 0201; Manufacturer: Panasonic Electronic Components; Manufacturer P/N: ERJ-1GEF4992C; Display Value: 49.9K, 0201; Temp Range: -55C - 125C
R40 R42 = RES_0071: Resistor, 62K, 1/20W, 1%, 0201; Manufacturer: Panasonic Electronic Components; Manufacturer P/N: P62.0KABDKR-ND; Display Value: 62K, 0201; Temp Range: -55C - 125C
U4 U6 = IC_0195: IC REG BUCK ADJ 1.2A SYNC 8WSON; Manufacturer: TI
U5 = IC_0199: IC REG BCK BST INV ADJ DL 24VQFN; Manufacturer: TI
U7 U8 = IC_0200: IC LED DRIVER 20TSSOP; Manufacturer: TI
U9 = IC_0118: 3.3 V LDO Voltage Regulators 250mA Ultra-Lo Noise LDO Reg; Manufacturer: TI; Manufacturer P/N: LP5907MFX-3.3NPB

## Sheet 0084 - Connectors.SchDoc: 0084 - AR Display Board
size Tabloid; Date: 3/18/2018; DrawnBy: Ryan Young; DocumentNumber: 1; Revision: 2.1; SheetNumber: 3; SheetTotal: 3; SheetTitle: Connectors; PageSetup: Record=PageOptions¦CenterHorizontal=True¦CenterVertical=True¦PrintScale=0.95¦XCorrection=1.00¦YCorrection=1.00¦PrintKind=0¦BorderSize=5000000¦LeftOffset=0¦BottomOffset=0¦Orientation=2¦PaperLength=1000¦PaperWidth=1000¦Scale=100¦PaperSource=15¦PrintQuality=600¦MediaType=1¦DitherType=10¦PaperKind=Letter (8.5 x 11")¦PrintScaleMode=1
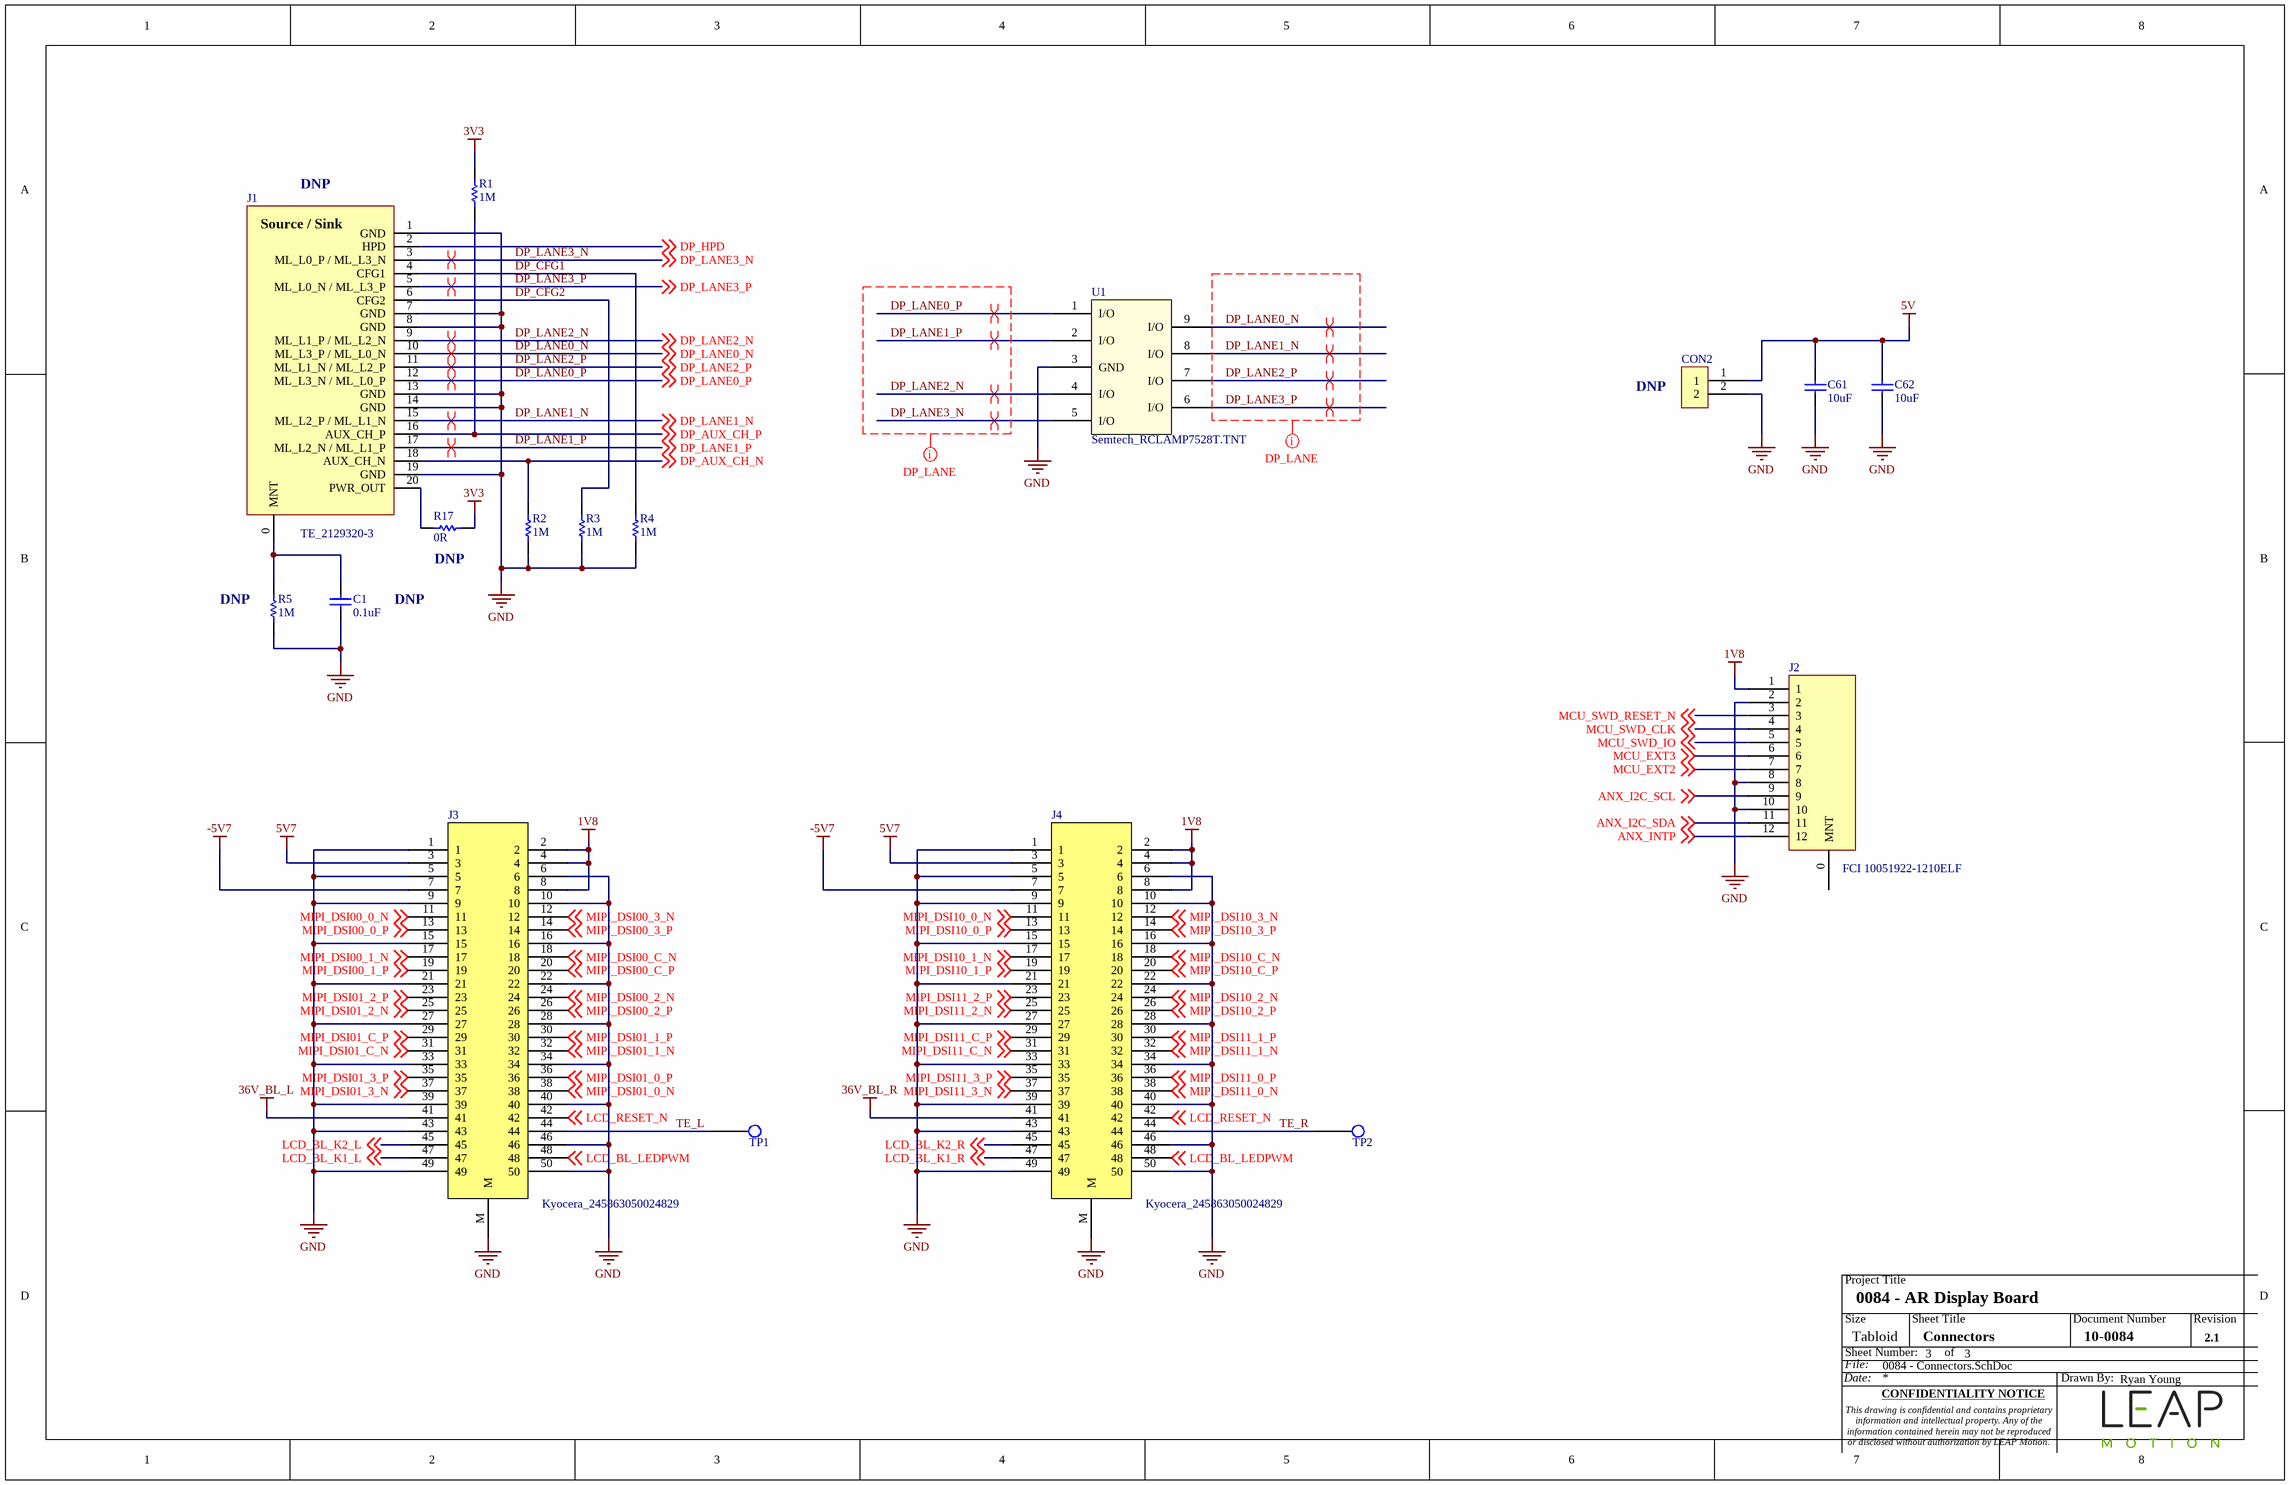
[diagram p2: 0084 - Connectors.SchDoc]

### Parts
C1  0.1uF  [CAPC0201(0603)33_N]  (no BOM)
C61  10uF  [CAPC1206(3216)170_N]
C62  10uF  [CAPC1206(3216)170_N]
CON2  CON2  [CON2_100mil]  (value not drawn)  (no BOM)
J1  TE_2129320-3  [TE_2129320-3]  (no BOM)
J2  FCI 10051922-1210ELF  [FCI 10051922-1210ELF]
J3  Kyocera_245863050024829  [Kyocera_245863050024829]
J4  Kyocera_245863050024829  [Kyocera_245863050024829]
R1  1M  [RESC0201(0603)_N]
R2  1M  [RESC0201(0603)_N]
R3  1M  [RESC0201(0603)_N]
R4  1M  [RESC0201(0603)_N]
R5  1M  [RESC0201(0603)_N]  (no BOM)
R17  0R  [RESC0402(1005)_N]  (no BOM)
TP1  TestPoint  [TestPointRnd-1_5mm]  (value not drawn)  (no BOM)
TP2  TestPoint  [TestPointRnd-1_5mm]  (value not drawn)  (no BOM)
U1  Semtech_RCLAMP7528T.TNT  [Semtech_RCLAMP7528T.TNT]

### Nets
1V8: J2.1 J3.2 J3.4 J3.8 J4.2 J4.4 J4.8
3V3: R1.2 R17.2
5V: C61.2 C62.2 CON2.1
5V7: J3.3 J4.3
36V_BL_L: J3.41
36V_BL_R: J4.41
-5V7: J3.7 J4.7
GND: C1.1 C61.1 C62.1 CON2.2 J1.1(GND) J1.7(GND) J1.8(GND) J1.13(GND) J1.14(GND) J1.19(GND) J2.2 J2.8 J2.10 J3.1 J3.5 J3.6 J3.9 J3.10 J3.15 J3.16 J3.21 J3.22 J3.27 J3.28 J3.33 J3.34 J3.39 J3.40 J3.43 J3.46 J3.49 J3.50 J3.M J4.1 J4.5 J4.6 J4.9 J4.10 J4.15 J4.16 J4.21 J4.22 J4.27 J4.28 J4.33 J4.34 J4.39 J4.40 J4.43 J4.46 J4.49 J4.50 J4.M R2.1 R3.1 R4.1 R5.1 U1.3(GND)
ANX_I2C_SCL: J2.9 ; off-sheet ANX_I2C_SCL
ANX_I2C_SDA: J2.11 ; off-sheet ANX_I2C_SDA
ANX_INTP: J2.12 ; off-sheet ANX_INTP
DP_AUX_CH_N: J1.18(AUX_CH_N) R2.2 ; off-sheet DP_AUX_CH_N
DP_AUX_CH_P: J1.16(AUX_CH_P) R1.1 ; off-sheet DP_AUX_CH_P
DP_CFG1: J1.4(CFG1) R4.2
DP_CFG2: J1.6(CFG2) R3.2
DP_HPD: J1.2(HPD) ; off-sheet DP_HPD
DP_LANE0_N: J1.10(ML_L3_P_/_ML_L0_N) U1.9(I/O) ; off-sheet DP_LANE0_N
DP_LANE0_P: J1.12(ML_L3_N_/_ML_L0_P) U1.1(I/O) ; off-sheet DP_LANE0_P
DP_LANE1_N: J1.15(ML_L2_P_/_ML_L1_N) U1.8(I/O) ; off-sheet DP_LANE1_N
DP_LANE1_P: J1.17(ML_L2_N_/_ML_L1_P) U1.2(I/O) ; off-sheet DP_LANE1_P
DP_LANE2_N: J1.9(ML_L1_P_/_ML_L2_N) U1.4(I/O) ; off-sheet DP_LANE2_N
DP_LANE2_P: J1.11(ML_L1_N_/_ML_L2_P) U1.7(I/O) ; off-sheet DP_LANE2_P
DP_LANE3_N: J1.3(ML_L0_P_/_ML_L3_N) U1.5(I/O) ; off-sheet DP_LANE3_N
DP_LANE3_P: J1.5(ML_L0_N_/_ML_L3_P) U1.6(I/O) ; off-sheet DP_LANE3_P
LCD_BL_K1_L: J3.47 ; off-sheet LCD_BL_K1_L
LCD_BL_K1_R: J4.47 ; off-sheet LCD_BL_K1_R
LCD_BL_K2_L: J3.45 ; off-sheet LCD_BL_K2_L
LCD_BL_K2_R: J4.45 ; off-sheet LCD_BL_K2_R
LCD_BL_LEDPWM: J3.48 J4.48 ; off-sheet LCD_BL_LEDPWM
LCD_RESET_N: J3.42 J4.42 ; off-sheet LCD_RESET_N
MCU_EXT2: J2.7 ; off-sheet MCU_EXT2
MCU_EXT3: J2.6 ; off-sheet MCU_EXT3
MCU_SWD_CLK: J2.4 ; off-sheet MCU_SWD_CLK
MCU_SWD_IO: J2.5 ; off-sheet MCU_SWD_IO
MCU_SWD_RESET_N: J2.3 ; off-sheet MCU_SWD_RESET_N
MIPI_DSI00_0_N: J3.11 ; off-sheet MIPI_DSI00_0_N
MIPI_DSI00_0_P: J3.13 ; off-sheet MIPI_DSI00_0_P
MIPI_DSI00_1_N: J3.17 ; off-sheet MIPI_DSI00_1_N
MIPI_DSI00_1_P: J3.19 ; off-sheet MIPI_DSI00_1_P
MIPI_DSI00_2_N: J3.24 ; off-sheet MIPI_DSI00_2_N
MIPI_DSI00_2_P: J3.26 ; off-sheet MIPI_DSI00_2_P
MIPI_DSI00_3_N: J3.12 ; off-sheet MIPI_DSI00_3_N
MIPI_DSI00_3_P: J3.14 ; off-sheet MIPI_DSI00_3_P
MIPI_DSI00_C_N: J3.18 ; off-sheet MIPI_DSI00_C_N
MIPI_DSI00_C_P: J3.20 ; off-sheet MIPI_DSI00_C_P
MIPI_DSI01_0_N: J3.38 ; off-sheet MIPI_DSI01_0_N
MIPI_DSI01_0_P: J3.36 ; off-sheet MIPI_DSI01_0_P
MIPI_DSI01_1_N: J3.32 ; off-sheet MIPI_DSI01_1_N
MIPI_DSI01_1_P: J3.30 ; off-sheet MIPI_DSI01_1_P
MIPI_DSI01_2_N: J3.25 ; off-sheet MIPI_DSI01_2_N
MIPI_DSI01_2_P: J3.23 ; off-sheet MIPI_DSI01_2_P
MIPI_DSI01_3_N: J3.37 ; off-sheet MIPI_DSI01_3_N
MIPI_DSI01_3_P: J3.35 ; off-sheet MIPI_DSI01_3_P
MIPI_DSI01_C_N: J3.31 ; off-sheet MIPI_DSI01_C_N
MIPI_DSI01_C_P: J3.29 ; off-sheet MIPI_DSI01_C_P
MIPI_DSI10_0_N: J4.11 ; off-sheet MIPI_DSI10_0_N
MIPI_DSI10_0_P: J4.13 ; off-sheet MIPI_DSI10_0_P
MIPI_DSI10_1_N: J4.17 ; off-sheet MIPI_DSI10_1_N
MIPI_DSI10_1_P: J4.19 ; off-sheet MIPI_DSI10_1_P
MIPI_DSI10_2_N: J4.24 ; off-sheet MIPI_DSI10_2_N
MIPI_DSI10_2_P: J4.26 ; off-sheet MIPI_DSI10_2_P
MIPI_DSI10_3_N: J4.12 ; off-sheet MIPI_DSI10_3_N
MIPI_DSI10_3_P: J4.14 ; off-sheet MIPI_DSI10_3_P
MIPI_DSI10_C_N: J4.18 ; off-sheet MIPI_DSI10_C_N
MIPI_DSI10_C_P: J4.20 ; off-sheet MIPI_DSI10_C_P
MIPI_DSI11_0_N: J4.38 ; off-sheet MIPI_DSI11_0_N
MIPI_DSI11_0_P: J4.36 ; off-sheet MIPI_DSI11_0_P
MIPI_DSI11_1_N: J4.32 ; off-sheet MIPI_DSI11_1_N
MIPI_DSI11_1_P: J4.30 ; off-sheet MIPI_DSI11_1_P
MIPI_DSI11_2_N: J4.25 ; off-sheet MIPI_DSI11_2_N
MIPI_DSI11_2_P: J4.23 ; off-sheet MIPI_DSI11_2_P
MIPI_DSI11_3_N: J4.37 ; off-sheet MIPI_DSI11_3_N
MIPI_DSI11_3_P: J4.35 ; off-sheet MIPI_DSI11_3_P
MIPI_DSI11_C_N: J4.31 ; off-sheet MIPI_DSI11_C_N
MIPI_DSI11_C_P: J4.29 ; off-sheet MIPI_DSI11_C_P
TE_L: J3.44 TP1.0
TE_R: J4.44 TP2.0
NetC1_2: C1.2 J1.0(MNT) R5.2
NetJ1_20: J1.20(PWR_OUT) R17.1

Not connected (* = marked no-connect by the designer): J2 0(MNT)

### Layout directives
differential pair: DP_LANE0_N, DP_LANE0_P, DP_LANE1_N, DP_LANE1_P, DP_LANE2_N, DP_LANE2_P, DP_LANE3_N, DP_LANE3_P
net class DP_LANE: DP_LANE0_N, DP_LANE0_P, DP_LANE1_N, DP_LANE1_P, DP_LANE2_N, DP_LANE2_P, DP_LANE3_N, DP_LANE3_P

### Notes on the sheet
- (near J1) DNP
- (near CON2) DNP
- (near R17) DNP
- (near R5) DNP
- DNP

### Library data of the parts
C1 = CAP_0060: as C2 on sheet 0084 - MCU
C61 C62 = CAP_0068: as C51 on sheet 0084 - Power
CON2 = CONN_0036: Connector, Generic, Header, 2POS, 2.54mm; Display Value: Generic Generic; Rows: 1
J1 = CONN_0094: Connector, TE Connectivity, Receptacle, 20POS, 0.9mm; Display Value: TE Connectivity 2129320-3; Mounting Height: 4.17mm; Temp Range: -40 - 85C; Rows: 2
J2 = CONN_0043: Connector, FCI, Right Angle, 12POS, 0.5mm; Mounting Height: 1.3mm; Temp Range: -55C - 85C; Rows: 1
J3 J4 = Kyocera_245863050024829: 245863050024829
R1-R5 = RES_0178: as R20 on sheet 0084 - MCU
R17 = RES_0006: as R16 on sheet 0084 - Power
TP1 TP2 = MISC_0052: Misc, TestPoint
U1 = IC_0201: TVS DIODE 5VWM 15VC SLP2611N9T

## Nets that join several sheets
1V: 0084 - MCU (5 pins), 0084 - Power (R24.2)
1V8: 0084 - MCU (22 pins), 0084 - Power (R32.2), 0084 - Connectors (7 pins)
3V3: 0084 - MCU (R23.1), 0084 - Power (R16.2), 0084 - Connectors (R1.2 R17.2)
5V: 0084 - MCU (D1.A D6.A), 0084 - Power (26 pins), 0084 - Connectors (C61.2 C62.2 CON2.1)
5V7: 0084 - Power (R18.2), 0084 - Connectors (J3.3 J4.3)
36V_BL_L: 0084 - Power (5 pins), 0084 - Connectors (J3.41)
36V_BL_R: 0084 - Power (5 pins), 0084 - Connectors (J4.41)
-5V7: 0084 - Power (R19.2), 0084 - Connectors (J3.7 J4.7)
GND: 0084 - MCU (56 pins), 0084 - Power (62 pins), 0084 - Connectors (58 pins)
ANX_I2C_SCL: 0084 - MCU (R7.1 U2.D10 U3.32), 0084 - Connectors (J2.9)
ANX_I2C_SDA: 0084 - MCU (R6.1 U2.C9 U3.31), 0084 - Connectors (J2.11)
ANX_INTP: 0084 - MCU (R8.1 U2.B4 U3.26), 0084 - Connectors (J2.12)
DP_AUX_CH_N: 0084 - MCU (C3.2 U2.A4), 0084 - Connectors (J1.18 R2.2)
DP_AUX_CH_P: 0084 - MCU (C2.2), 0084 - Connectors (J1.16 R1.1)
DP_HPD: 0084 - MCU (Q1.3 R23.2), 0084 - Connectors (J1.2)
DP_LANE0_N: 0084 - MCU (U2.A5), 0084 - Connectors (J1.10 U1.9)
DP_LANE0_P: 0084 - MCU (U2.B5), 0084 - Connectors (J1.12 U1.1)
DP_LANE1_N: 0084 - MCU (U2.A6), 0084 - Connectors (J1.15 U1.8)
DP_LANE1_P: 0084 - MCU (U2.B6), 0084 - Connectors (J1.17 U1.2)
DP_LANE2_N: 0084 - MCU (U2.A7), 0084 - Connectors (J1.9 U1.4)
DP_LANE2_P: 0084 - MCU (U2.B7), 0084 - Connectors (J1.11 U1.7)
DP_LANE3_N: 0084 - MCU (U2.A8), 0084 - Connectors (J1.3 U1.5)
DP_LANE3_P: 0084 - MCU (U2.B8), 0084 - Connectors (J1.5 U1.6)
LCD_BIAS_EN: 0084 - MCU (U3.7), 0084 - Power (U5.8 U5.9 U5.10 U5.11)
LCD_BL_EN: 0084 - MCU (U3.8), 0084 - Power (U7.4 U7.6 U8.4 U8.6)
LCD_BL_FAULT: 0084 - MCU (R10.1 U3.30), 0084 - Power (U7.5 U8.5)
LCD_BL_K1_L: 0084 - Power (U7.14), 0084 - Connectors (J3.47)
LCD_BL_K1_R: 0084 - Power (U8.14), 0084 - Connectors (J4.47)
LCD_BL_K2_L: 0084 - Power (U7.15), 0084 - Connectors (J3.45)
LCD_BL_K2_R: 0084 - Power (U8.15), 0084 - Connectors (J4.45)
LCD_BL_LEDPWM: 0084 - MCU (U3.12), 0084 - Connectors (J3.48 J4.48)
LCD_BL_PWM: 0084 - MCU (U3.11), 0084 - Power (U7.7 U8.7)
LCD_RESET_N: 0084 - MCU (R12.1 U3.14), 0084 - Connectors (J3.42 J4.42)
MCU_EXT2: 0084 - MCU (U3.37), 0084 - Connectors (J2.7)
MCU_EXT3: 0084 - MCU (U3.38), 0084 - Connectors (J2.6)
MCU_SWD_CLK: 0084 - MCU (R9.1 U3.45), 0084 - Connectors (J2.4)
MCU_SWD_IO: 0084 - MCU (U3.46), 0084 - Connectors (J2.5)
MCU_SWD_RESET_N: 0084 - MCU (R13.1), 0084 - Connectors (J2.3)
MIPI_DSI00_0_N: 0084 - MCU (U2.J5), 0084 - Connectors (J3.11)
MIPI_DSI00_0_P: 0084 - MCU (U2.K5), 0084 - Connectors (J3.13)
MIPI_DSI00_1_N: 0084 - MCU (U2.J7), 0084 - Connectors (J3.17)
MIPI_DSI00_1_P: 0084 - MCU (U2.K7), 0084 - Connectors (J3.19)
MIPI_DSI00_2_N: 0084 - MCU (U2.J8), 0084 - Connectors (J3.24)
MIPI_DSI00_2_P: 0084 - MCU (U2.K8), 0084 - Connectors (J3.26)
MIPI_DSI00_3_N: 0084 - MCU (U2.J4), 0084 - Connectors (J3.12)
MIPI_DSI00_3_P: 0084 - MCU (U2.K4), 0084 - Connectors (J3.14)
MIPI_DSI00_C_N: 0084 - MCU (U2.J6), 0084 - Connectors (J3.18)
MIPI_DSI00_C_P: 0084 - MCU (U2.K6), 0084 - Connectors (J3.20)
MIPI_DSI01_0_N: 0084 - MCU (U2.G9), 0084 - Connectors (J3.38)
MIPI_DSI01_0_P: 0084 - MCU (U2.G10), 0084 - Connectors (J3.36)
MIPI_DSI01_1_N: 0084 - MCU (U2.J10), 0084 - Connectors (J3.32)
MIPI_DSI01_1_P: 0084 - MCU (U2.K10), 0084 - Connectors (J3.30)
MIPI_DSI01_2_N: 0084 - MCU (U2.J9), 0084 - Connectors (J3.25)
MIPI_DSI01_2_P: 0084 - MCU (U2.K9), 0084 - Connectors (J3.23)
MIPI_DSI01_3_N: 0084 - MCU (U2.F9), 0084 - Connectors (J3.37)
MIPI_DSI01_3_P: 0084 - MCU (U2.F10), 0084 - Connectors (J3.35)
MIPI_DSI01_C_N: 0084 - MCU (U2.H9), 0084 - Connectors (J3.31)
MIPI_DSI01_C_P: 0084 - MCU (U2.H10), 0084 - Connectors (J3.29)
MIPI_DSI10_0_N: 0084 - MCU (U2.C1), 0084 - Connectors (J4.11)
MIPI_DSI10_0_P: 0084 - MCU (U2.C2), 0084 - Connectors (J4.13)
MIPI_DSI10_1_N: 0084 - MCU (U2.E1), 0084 - Connectors (J4.17)
MIPI_DSI10_1_P: 0084 - MCU (U2.E2), 0084 - Connectors (J4.19)
MIPI_DSI10_2_N: 0084 - MCU (U2.F1), 0084 - Connectors (J4.24)
MIPI_DSI10_2_P: 0084 - MCU (U2.F2), 0084 - Connectors (J4.26)
MIPI_DSI10_3_N: 0084 - MCU (U2.B1), 0084 - Connectors (J4.12)
MIPI_DSI10_3_P: 0084 - MCU (U2.B2), 0084 - Connectors (J4.14)
MIPI_DSI10_C_N: 0084 - MCU (U2.D1), 0084 - Connectors (J4.18)
MIPI_DSI10_C_P: 0084 - MCU (U2.D2), 0084 - Connectors (J4.20)
MIPI_DSI11_0_N: 0084 - MCU (U2.K1), 0084 - Connectors (J4.38)
MIPI_DSI11_0_P: 0084 - MCU (U2.K2), 0084 - Connectors (J4.36)
MIPI_DSI11_1_N: 0084 - MCU (U2.H1), 0084 - Connectors (J4.32)
MIPI_DSI11_1_P: 0084 - MCU (U2.H2), 0084 - Connectors (J4.30)
MIPI_DSI11_2_N: 0084 - MCU (U2.G1), 0084 - Connectors (J4.25)
MIPI_DSI11_2_P: 0084 - MCU (U2.G2), 0084 - Connectors (J4.23)
MIPI_DSI11_3_N: 0084 - MCU (U2.J3), 0084 - Connectors (J4.37)
MIPI_DSI11_3_P: 0084 - MCU (U2.K3), 0084 - Connectors (J4.35)
MIPI_DSI11_C_N: 0084 - MCU (U2.J1), 0084 - Connectors (J4.31)
MIPI_DSI11_C_P: 0084 - MCU (U2.J2), 0084 - Connectors (J4.29)

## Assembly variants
Variant of 0084 - AR Display Board Rev2.0: not fitted C1 CON2 J1 R5 R17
